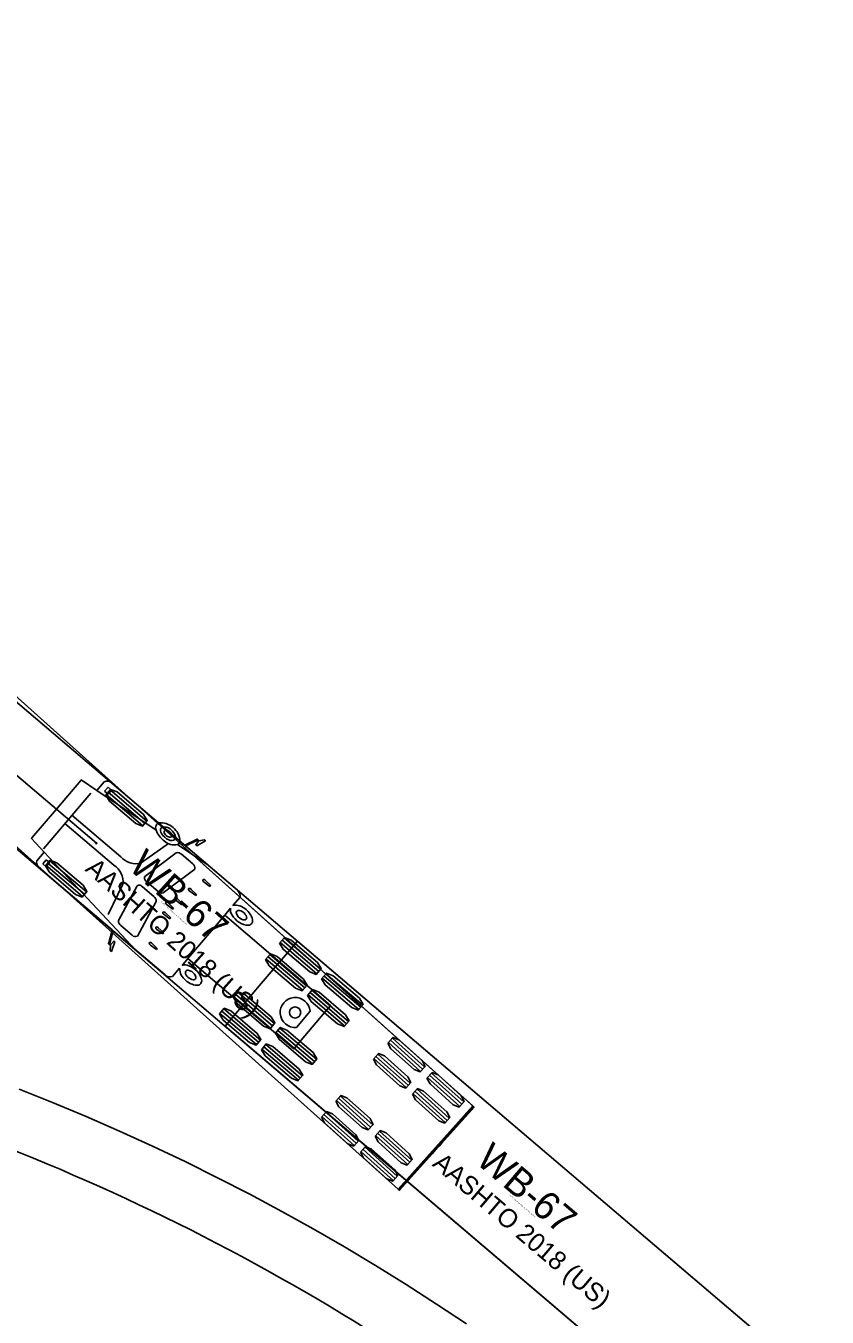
# Model space of a CAD drawing. Extents: x 973688 to 979179, y 703586 to 707602.
# Drawn here: x 974145.9 to 974206.9, y 707275.4 to 707373.8 of the extents above; entities that cross this region are included whole.
import ezdxf

# ---------------------------------------------------------------- set-up
doc = ezdxf.new("R2010")
doc.units = 0
doc.layers.add('0-NPLT', color=7, linetype='Continuous')
doc.layers.add('NO PLOT', color=7, linetype='Continuous')

msp = doc.modelspace()

# ---------------------------------------------------------------- linework, layer by layer
at = {"layer": '0-NPLT'}
for p, q in [((974173.518, 707296.32), (974175.975, 707294.117)), ((974173.518, 707296.32), (974175.975, 707294.117)), ((974173.671, 707296.49), (974176.128, 707294.287)), ((974173.671, 707296.49), (974176.128, 707294.287)), ((974173.824, 707296.661), (974176.281, 707294.458)), ((974173.824, 707296.661), (974176.281, 707294.458)), ((974172.417, 707295.091), (974174.874, 707292.888)), ((974172.417, 707295.091), (974174.874, 707292.888)), ((974172.57, 707295.262), (974175.027, 707293.059)), ((974172.57, 707295.262), (974175.027, 707293.059)), ((974172.723, 707295.432), (974175.18, 707293.229)), ((974172.723, 707295.432), (974175.18, 707293.229)), ((974176.65, 707293.82), (974179.107, 707291.617)), ((974176.65, 707293.82), (974179.107, 707291.617)), ((974176.803, 707293.991), (974179.26, 707291.788)), ((974176.803, 707293.991), (974179.26, 707291.788)), ((974175.701, 707292.762), (974178.158, 707290.559)), ((974175.701, 707292.762), (974178.158, 707290.559)), ((974176.497, 707293.649), (974178.954, 707291.446)), ((974176.497, 707293.649), (974178.954, 707291.446)), ((974169.557, 707291.902), (974172.014, 707289.699)), ((974169.557, 707291.902), (974172.014, 707289.699)), ((974169.71, 707292.073), (974172.167, 707289.87)), ((974169.71, 707292.073), (974172.167, 707289.87)), ((974169.863, 707292.243), (974172.32, 707290.04)), ((974169.863, 707292.243), (974172.32, 707290.04)), ((974175.395, 707292.421), (974177.852, 707290.218)), ((974175.395, 707292.421), (974177.852, 707290.218)), ((974175.548, 707292.591), (974178.005, 707290.388)), ((974175.548, 707292.591), (974178.005, 707290.388)), ((974168.609, 707290.844), (974171.066, 707288.641)), ((974168.609, 707290.844), (974171.066, 707288.641)), ((974168.762, 707291.015), (974171.219, 707288.812)), ((974168.762, 707291.015), (974171.219, 707288.812)), ((974179.94, 707291.485), (974174.266, 707285.156)), ((974179.94, 707291.485), (974174.266, 707285.156)), ((974168.456, 707290.674), (974170.913, 707288.471)), ((974168.456, 707290.674), (974170.913, 707288.471)), ((974172.536, 707289.232), (974174.993, 707287.029)), ((974172.536, 707289.232), (974174.993, 707287.029)), ((974172.689, 707289.402), (974175.146, 707287.199)), ((974172.689, 707289.402), (974175.146, 707287.199)), ((974172.842, 707289.573), (974175.299, 707287.37)), ((974172.842, 707289.573), (974175.299, 707287.37)), ((974171.434, 707288.003), (974173.891, 707285.8)), ((974171.434, 707288.003), (974173.891, 707285.8)), ((974171.587, 707288.174), (974174.044, 707285.971)), ((974171.587, 707288.174), (974174.044, 707285.971)), ((974171.74, 707288.345), (974174.197, 707286.142)), ((974171.74, 707288.345), (974174.197, 707286.142)), ((974176.978, 707288.076), (974176.801, 707287.878)), ((974176.978, 707288.076), (974176.801, 707287.878)), ((974177.156, 707288.274), (974177.103, 707288.321)), ((974177.156, 707288.274), (974177.103, 707288.321)), ((974177.51, 707288.669), (974177.333, 707288.471)), ((974177.51, 707288.669), (974177.333, 707288.471))]:
    msp.add_line(p, q, dxfattribs=at)
for points in [[(974091.775, 707370.47), (974093.475, 707368.994), (974180.045, 707291.391), (974174.371, 707285.062), (974174.274, 707285.149), (974174.274, 707285.149)], [(974091.775, 707370.47), (974093.475, 707368.994), (974180.045, 707291.391), (974174.371, 707285.062), (974174.274, 707285.149), (974174.274, 707285.149)], [(974174.274, 707285.149), (974119.818, 707333.965), (974115.987, 707337.353), (974112.281, 707340.555), (974110.488, 707342.064), (974108.732, 707343.506), (974107.011, 707344.881), (974105.317, 707346.189), (974103.645, 707347.433), (974101.988, 707348.612), (974100.348, 707349.725), (974098.726, 707350.769), (974097.122, 707351.743), (974095.538, 707352.645), (974093.977, 707353.475), (974092.437, 707354.233)], [(974174.274, 707285.149), (974119.818, 707333.965), (974115.987, 707337.353), (974112.281, 707340.555), (974110.488, 707342.064), (974108.732, 707343.506), (974107.011, 707344.881), (974105.317, 707346.189), (974103.645, 707347.433), (974101.988, 707348.612), (974100.348, 707349.725), (974098.726, 707350.769), (974097.122, 707351.743), (974095.538, 707352.645), (974093.977, 707353.475), (974092.437, 707354.233)], [(974179.978, 707291.421), (974179.992, 707291.437), (974179.94, 707291.484), (974175.721, 707295.268), (974140.585, 707326.772), (974137.748, 707323.608), (974134.91, 707320.444), (974170.046, 707288.94), (974174.266, 707285.157), (974174.319, 707285.11), (974174.333, 707285.126)], [(974179.978, 707291.421), (974179.992, 707291.437), (974179.94, 707291.484), (974175.721, 707295.268), (974140.585, 707326.772), (974137.748, 707323.608), (974134.91, 707320.444), (974170.046, 707288.94), (974174.266, 707285.157), (974174.319, 707285.11), (974174.333, 707285.126)], [(974145.394, 707292.754), (974147.934, 707291.742), (974150.486, 707290.678), (974153.02, 707289.573), (974155.535, 707288.429), (974158.03, 707287.245), (974160.505, 707286.022), (974162.958, 707284.76), (974165.389, 707283.459), (974167.797, 707282.122), (974170.182, 707280.746), (974172.543, 707279.334), (974174.88, 707277.886), (974177.192, 707276.401), (974179.478, 707274.881)], [(974145.394, 707292.754), (974147.934, 707291.742), (974150.486, 707290.678), (974153.02, 707289.573), (974155.535, 707288.429), (974158.03, 707287.245), (974160.505, 707286.022), (974162.958, 707284.76), (974165.389, 707283.459), (974167.797, 707282.122), (974170.182, 707280.746), (974172.543, 707279.334), (974174.88, 707277.886), (974177.192, 707276.401), (974179.478, 707274.881)], [(974177.384, 707288.422), (974177.562, 707288.621), (974177.562, 707288.622), (974177.51, 707288.669), (974177.534, 707288.696), (974179.961, 707291.403), (974179.962, 707291.403)], [(974177.384, 707288.422), (974177.562, 707288.621), (974177.562, 707288.622), (974177.51, 707288.669), (974177.534, 707288.696), (974179.961, 707291.403), (974179.962, 707291.403)], [(974174.35, 707285.144), (974174.35, 707285.145), (974176.777, 707287.851), (974176.801, 707287.878), (974176.853, 707287.831), (974176.854, 707287.832), (974177.033, 707288.031)], [(974174.35, 707285.144), (974174.35, 707285.145), (974176.777, 707287.851), (974176.801, 707287.878), (974176.853, 707287.831), (974176.854, 707287.832), (974177.033, 707288.031)], [(974176.983, 707288.081), (974177.331, 707288.469)], [(974176.983, 707288.081), (974177.331, 707288.469)]]:
    msp.add_lwpolyline(points, dxfattribs=at)
for points in [[(974173.481, 707296.277), (974173.862, 707296.703), (974174.321, 707296.523), (974176.09, 707294.937), (974176.319, 707294.5), (974175.937, 707294.074), (974175.478, 707294.254), (974173.709, 707295.841)], [(974173.481, 707296.277), (974173.862, 707296.703), (974174.321, 707296.523), (974176.09, 707294.937), (974176.319, 707294.5), (974175.937, 707294.074), (974175.478, 707294.254), (974173.709, 707295.841)], [(974172.379, 707295.049), (974172.761, 707295.475), (974173.22, 707295.295), (974174.989, 707293.708), (974175.218, 707293.272), (974174.836, 707292.846), (974174.377, 707293.026), (974172.608, 707294.612)], [(974172.379, 707295.049), (974172.761, 707295.475), (974173.22, 707295.295), (974174.989, 707293.708), (974175.218, 707293.272), (974174.836, 707292.846), (974174.377, 707293.026), (974172.608, 707294.612)], [(974176.459, 707293.607), (974176.841, 707294.033), (974177.3, 707293.853), (974179.069, 707292.267), (974179.297, 707291.83), (974178.916, 707291.404), (974178.457, 707291.584), (974176.688, 707293.17)], [(974176.459, 707293.607), (974176.841, 707294.033), (974177.3, 707293.853), (974179.069, 707292.267), (974179.297, 707291.83), (974178.916, 707291.404), (974178.457, 707291.584), (974176.688, 707293.17)], [(974175.357, 707292.379), (974175.739, 707292.804), (974176.198, 707292.624), (974177.967, 707291.038), (974178.196, 707290.601), (974177.814, 707290.176), (974177.355, 707290.356), (974175.586, 707291.942)], [(974175.357, 707292.379), (974175.739, 707292.804), (974176.198, 707292.624), (974177.967, 707291.038), (974178.196, 707290.601), (974177.814, 707290.176), (974177.355, 707290.356), (974175.586, 707291.942)], [(974169.52, 707291.86), (974169.901, 707292.286), (974170.36, 707292.106), (974172.129, 707290.519), (974172.358, 707290.083), (974171.977, 707289.657), (974171.517, 707289.837), (974169.748, 707291.423)], [(974169.52, 707291.86), (974169.901, 707292.286), (974170.36, 707292.106), (974172.129, 707290.519), (974172.358, 707290.083), (974171.977, 707289.657), (974171.517, 707289.837), (974169.748, 707291.423)], [(974168.418, 707290.631), (974168.8, 707291.057), (974169.259, 707290.877), (974171.028, 707289.291), (974171.257, 707288.854), (974170.875, 707288.428), (974170.416, 707288.608), (974168.647, 707290.195)], [(974168.418, 707290.631), (974168.8, 707291.057), (974169.259, 707290.877), (974171.028, 707289.291), (974171.257, 707288.854), (974170.875, 707288.428), (974170.416, 707288.608), (974168.647, 707290.195)], [(974172.498, 707289.189), (974172.88, 707289.615), (974173.339, 707289.435), (974175.108, 707287.849), (974175.337, 707287.412), (974174.955, 707286.986), (974174.496, 707287.167), (974172.727, 707288.753)], [(974172.498, 707289.189), (974172.88, 707289.615), (974173.339, 707289.435), (974175.108, 707287.849), (974175.337, 707287.412), (974174.955, 707286.986), (974174.496, 707287.167), (974172.727, 707288.753)], [(974171.396, 707287.961), (974171.778, 707288.387), (974172.237, 707288.207), (974174.006, 707286.621), (974174.235, 707286.184), (974173.853, 707285.758), (974173.394, 707285.938), (974171.625, 707287.524)], [(974171.396, 707287.961), (974171.778, 707288.387), (974172.237, 707288.207), (974174.006, 707286.621), (974174.235, 707286.184), (974173.853, 707285.758), (974173.394, 707285.938), (974171.625, 707287.524)]]:
    msp.add_lwpolyline(points, close=True, dxfattribs=at)
for centre in [(974179.995, 707291.39), (974179.995, 707291.39), (974174.367, 707285.112), (974174.367, 707285.112)]:
    msp.add_circle(centre, 0.0266, dxfattribs=at)
for centre, radius, start, end in [((974082.791, 707131.948), 168.088, 48.27288, 72.23933), ((974082.791, 707131.948), 168.088, 48.27288, 72.23933), ((974181.483, 707290.071), 2.022, 138.11946, 138.80322), ((974181.483, 707290.071), 2.022, 138.11946, 138.80322), ((974177.006, 707288.054), 0.0353, 141.45563, 319.80529), ((974177.006, 707288.054), 0.0353, 141.45563, 319.80529), ((974177.006, 707288.054), 0.0352, 318.14472, 137.14513), ((974177.006, 707288.054), 0.0352, 318.14472, 137.14513), ((974177.357, 707288.446), 0.0352, 139.09378, 318.09419), ((974177.357, 707288.446), 0.0352, 139.09378, 318.09419), ((974177.358, 707288.446), 0.0354, 322.41099, 134.59646), ((974177.358, 707288.446), 0.0354, 322.41099, 134.59646), ((974174.367, 707285.112), 0.0363, 157.1969, 118.35825), ((974174.367, 707285.112), 0.0363, 157.1969, 118.35825)]:
    msp.add_arc(centre, radius, start, end, dxfattribs=at)
at = {"layer": 'NO PLOT'}
for p, q in [((974151.267, 707311.497), (974078.117, 707373.753)), ((974155.816, 707312.493), (974151.31, 707315.518)), ((974152.162, 707315.779), (974151.894, 707315.465)), ((974151.894, 707315.465), (974152.165, 707315.234)), ((974152.433, 707315.548), (974152.162, 707315.779)), ((974152.165, 707315.234), (974152.433, 707315.548)), ((974152.166, 707315.382), (974154.958, 707313.006)), ((974152.315, 707315.557), (974155.107, 707313.18)), ((974150.844, 707315.319), (974147.239, 707311.082)), ((974152.018, 707315.208), (974154.81, 707312.831)), ((974149.406, 707313.629), (974153.131, 707310.458)), ((974148.865, 707312.993), (974152.59, 707309.823)), ((974154.68, 707309.996), (974156.772, 707311.473)), ((974159.054, 707311.644), (974159.072, 707311.666)), ((974159.072, 707311.666), (974159.099, 707311.672)), ((974154.27, 707303.36), (974147.304, 707310.812)), ((974157.357, 707310.77), (974154.963, 707308.952)), ((974159.779, 707309.833), (974157.449, 707311.397)), ((974158.607, 707309.923), (974157.746, 707310.656)), ((974158.066, 707311.291), (974157.99, 707311.356)), ((974147.183, 707309.929), (974147.45, 707310.243)), ((974147.454, 707309.698), (974147.183, 707309.929)), ((974147.427, 707309.814), (974150.219, 707307.437)), ((974147.45, 707310.243), (974147.721, 707310.013)), ((974147.721, 707310.013), (974147.454, 707309.698)), ((974147.575, 707309.988), (974150.367, 707307.612)), ((974147.724, 707310.163), (974150.516, 707307.786)), ((974156.367, 707307.714), (974158.76, 707309.532)), ((974155.116, 707308.561), (974155.977, 707307.828)), ((974159.919, 707308.199), (974159.475, 707308.525)), ((974159.584, 707308.653), (974159.978, 707308.267)), ((974153.294, 707308.367), (974152.177, 707306.078)), ((974152.958, 707305.602), (974154.37, 707308.255)), ((974154.781, 707308.166), (974155.642, 707307.433)), ((974158.837, 707307.522), (974158.393, 707307.848)), ((974158.502, 707307.976), (974158.895, 707307.59)), ((974158.895, 707307.59), (974158.837, 707307.522)), ((974159.978, 707308.267), (974159.919, 707308.199)), ((974155.816, 707307.068), (974154.404, 707304.414)), ((974157.1, 707306.473), (974156.656, 707306.8)), ((974156.765, 707306.928), (974157.158, 707306.542)), ((974157.158, 707306.542), (974157.1, 707306.473)), ((974157.793, 707306.811), (974157.349, 707307.138)), ((974157.458, 707307.266), (974157.851, 707306.88)), ((974157.851, 707306.88), (974157.793, 707306.811)), ((974156.877, 707305.735), (974156.433, 707306.062)), ((974156.542, 707306.19), (974156.935, 707305.804)), ((974156.935, 707305.804), (974156.877, 707305.735)), ((974161.047, 707306.016), (974158.24, 707302.719)), ((974152.557, 707304.818), (974152.481, 707304.883)), ((974153.994, 707304.503), (974153.133, 707305.236)), ((974156.343, 707304.592), (974155.879, 707304.934)), ((974155.988, 707305.062), (974156.401, 707304.66)), ((974156.401, 707304.66), (974156.343, 707304.592)), ((974152.348, 707303.766), (974152.346, 707303.738)), ((974152.367, 707303.786), (974152.348, 707303.766)), ((974155.847, 707303.415), (974155.403, 707303.741)), ((974155.512, 707303.869), (974155.906, 707303.483)), ((974165.268, 707303.93), (974168.061, 707301.554)), ((974165.417, 707304.105), (974168.209, 707301.728)), ((974165.565, 707304.279), (974168.358, 707301.903)), ((974155.906, 707303.483), (974155.847, 707303.415)), ((974164.199, 707302.674), (974166.991, 707300.297)), ((974164.347, 707302.848), (974167.14, 707300.472)), ((974164.496, 707303.023), (974167.288, 707300.646)), ((974168.467, 707301.208), (974171.259, 707298.832)), ((974168.615, 707301.383), (974171.407, 707299.006)), ((974168.764, 707301.557), (974171.556, 707299.181)), ((974161.747, 707299.793), (974164.539, 707297.416)), ((974161.895, 707299.967), (974164.688, 707297.591)), ((974162.044, 707300.142), (974164.836, 707297.765)), ((974167.397, 707299.952), (974170.19, 707297.575)), ((974167.546, 707300.126), (974170.338, 707297.75)), ((974167.694, 707300.301), (974170.487, 707297.924)), ((974160.826, 707298.711), (974163.618, 707296.334)), ((974160.974, 707298.885), (974163.767, 707296.509)), ((974166.509, 707297.47), (974167.556, 707298.701)), ((974160.677, 707298.536), (974163.47, 707296.16)), ((974164.945, 707297.071), (974167.737, 707294.694)), ((974165.094, 707297.245), (974167.886, 707294.869)), ((974165.242, 707297.42), (974168.035, 707295.043)), ((974163.876, 707295.814), (974166.668, 707293.438)), ((974164.024, 707295.989), (974166.817, 707293.612)), ((974164.173, 707296.163), (974166.965, 707293.787))]:
    msp.add_line(p, q, dxfattribs=at)
for points in [[(974090.217, 707369.015), (974206.948, 707269.689), (974201.439, 707263.216), (974201.341, 707263.299), (974201.341, 707263.299)], [(974201.341, 707263.299), (974117.082, 707334.995), (974113.179, 707338.264), (974109.412, 707341.341), (974107.59, 707342.787), (974105.806, 707344.168), (974104.057, 707345.482), (974102.335, 707346.731), (974100.634, 707347.916), (974098.951, 707349.037), (974097.285, 707350.092), (974095.639, 707351.077), (974094.014, 707351.993), (974092.411, 707352.837)], [(974146.744, 707310.153), (974147.299, 707310.805), (974147.303, 707310.813), (974146.324, 707311.861), (974146.365, 707311.909), (974148.221, 707314.089), (974150.076, 707316.27), (974150.118, 707316.318), (974151.308, 707315.519), (974151.315, 707315.524), (974151.87, 707316.177)], [(974152.458, 707316.064), (974155.995, 707313.054)], [(974157.659, 707311.637), (974157.984, 707311.361), (974157.999, 707311.36), (974158.901, 707311.781)], [(974159.032, 707311.728), (974159.098, 707311.673), (974159.101, 707311.673), (974159.488, 707311.76), (974159.491, 707311.76), (974159.581, 707311.684), (974159.581, 707311.682), (974158.918, 707311.301), (974158.84, 707311.367), (974159.054, 707311.643), (974159.054, 707311.644), (974158.992, 707311.695), (974158.992, 707311.696), (974158.991, 707311.696), (974158.955, 707311.711), (974158.955, 707311.711), (974158.066, 707311.291), (974162.008, 707307.936)], [(974152.207, 707303.915), (974152.478, 707304.873), (974152.475, 707304.888), (974146.948, 707309.591)], [(974161.492, 707306.539), (974161.047, 707306.017), (974161.228, 707305.862), (974169.119, 707299.146), (974167.716, 707297.497), (974166.313, 707295.849), (974158.422, 707302.564), (974158.24, 707302.718), (974157.795, 707302.196)], [(974162.222, 707307.398), (974161.675, 707306.754)], [(974156.499, 707301.463), (974152.557, 707304.818), (974152.285, 707303.873), (974152.285, 707303.873), (974152.305, 707303.84), (974152.305, 707303.84), (974152.306, 707303.839), (974152.366, 707303.787), (974152.368, 707303.787), (974152.605, 707304.042), (974152.684, 707303.975), (974152.413, 707303.26), (974152.412, 707303.259), (974152.321, 707303.336), (974152.321, 707303.34), (974152.346, 707303.736), (974152.345, 707303.739), (974152.28, 707303.795)], [(974206.88, 707269.717), (974206.894, 707269.734), (974206.84, 707269.78), (974202.525, 707273.453), (974166.587, 707304.039), (974163.832, 707300.803), (974161.078, 707297.566), (974197.016, 707266.98), (974201.332, 707263.308), (974201.386, 707263.262), (974201.4, 707263.279)], [(974157.613, 707301.981), (974157.065, 707301.338)]]:
    msp.add_lwpolyline(points, dxfattribs=at)
for points in [[(974151.981, 707315.164), (974152.351, 707315.6), (974152.854, 707315.399), (974154.864, 707313.688), (974155.144, 707313.224), (974154.773, 707312.788), (974154.27, 707312.99), (974152.26, 707314.701)], [(974147.39, 707309.77), (974147.761, 707310.206), (974148.263, 707310.004), (974150.274, 707308.293), (974150.553, 707307.829), (974150.182, 707307.394), (974149.679, 707307.595), (974147.669, 707309.306)], [(974165.231, 707303.887), (974165.602, 707304.323), (974166.105, 707304.121), (974168.115, 707302.41), (974168.394, 707301.946), (974168.024, 707301.511), (974167.521, 707301.712), (974165.511, 707303.423)], [(974164.162, 707302.631), (974164.533, 707303.066), (974165.035, 707302.865), (974167.046, 707301.154), (974167.325, 707300.69), (974166.954, 707300.254), (974166.452, 707300.456), (974164.441, 707302.167)], [(974168.43, 707301.165), (974168.801, 707301.601), (974169.303, 707301.399), (974171.314, 707299.688), (974171.593, 707299.224), (974171.222, 707298.789), (974170.72, 707298.99), (974168.709, 707300.701)], [(974161.71, 707299.749), (974162.081, 707300.185), (974162.583, 707299.984), (974164.594, 707298.273), (974164.873, 707297.809), (974164.502, 707297.373), (974164, 707297.574), (974161.989, 707299.286)], [(974167.36, 707299.908), (974167.731, 707300.344), (974168.234, 707300.143), (974170.244, 707298.432), (974170.523, 707297.968), (974170.153, 707297.532), (974169.65, 707297.733), (974167.64, 707299.445)], [(974160.641, 707298.493), (974161.011, 707298.929), (974161.514, 707298.727), (974163.524, 707297.016), (974163.804, 707296.552), (974163.433, 707296.116), (974162.93, 707296.318), (974160.92, 707298.029)], [(974164.908, 707297.027), (974165.279, 707297.463), (974165.782, 707297.261), (974167.792, 707295.55), (974168.071, 707295.086), (974167.701, 707294.651), (974167.198, 707294.852), (974165.188, 707296.563)], [(974163.839, 707295.771), (974164.21, 707296.206), (974164.712, 707296.005), (974166.723, 707294.294), (974167.002, 707293.83), (974166.631, 707293.394), (974166.129, 707293.596), (974164.118, 707295.307)]]:
    msp.add_lwpolyline(points, close=True, dxfattribs=at)
for centre, radius in [((974151.267, 707311.497), 0.0417), ((974166.412, 707298.607), 0.424)]:
    msp.add_circle(centre, radius, dxfattribs=at)
for centre, radius, start, end in [((974152.092, 707315.744), 0.486, 41.18554, 117.13665), ((974156.204, 707312.668), 0.425, 117.66255, 204.19891), ((974157.422, 707313.063), 1.704, 199.5203, 235.42836), ((974156.131, 707311.53), 1.53, 4.09235, 95.1014), ((974156.516, 707312.47), 0.366, 147.65195, 220.13294), ((974156.487, 707312.097), 0.634, 40.18347, 116.18519), ((974156.588, 707312.359), 0.158, 144.57083, 206.08358), ((974156.592, 707312.271), 0.223, 56.83451, 126.43701), ((974156.468, 707311.922), 0.589, 22.35514, 65.33785), ((974156.32, 707311.708), 1.03, 22.42326, 50.80977), ((974157.259, 707312.842), 1.189, 210.73081, 246.62013), ((974156.978, 707312.512), 0.575, 202.67473, 239.24506), ((974157.211, 707312.508), 1.136, 228.30415, 282.10672), ((974156.857, 707312.214), 0.263, 228.53452, 302.43645), ((974156.997, 707312.137), 0.44, 241.39386, 305.2067), ((974156.855, 707312.084), 0.17, 327.26867, 21.33301), ((974156.99, 707311.957), 0.317, 325.44981, 27.04221), ((974157.319, 707311.719), 0.347, 291.92682, 346.73741), ((974158.948, 707311.758), 0.0522, 48.48221, 153.33683), ((974158.927, 707311.705), 0.108, 12.57594, 58.75844), ((974154.272, 707311.457), 1.517, 221.17966, 285.60707), ((974157.458, 707310.397), 0.387, 42.0348, 105.26676), ((974147.206, 707310.003), 0.486, 162.06257, 238.01368), ((974151.787, 707308.536), 1.517, 353.59215, 58.01957), ((974158.444, 707309.633), 0.332, 342.25621, 60.67821), ((974155.234, 707308.833), 0.296, 156.31837, 246.61605), ((974159.56, 707308.689), 0.184, 170.75441, 242.64643), ((974159.447, 707308.578), 0.157, 28.94397, 116.05363), ((974154.531, 707308.007), 0.296, 32.58318, 122.88085), ((974156.265, 707308.087), 0.387, 222.03725, 285.26431), ((974158.477, 707308.012), 0.184, 170.75441, 242.64643), ((974158.364, 707307.9), 0.157, 28.94397, 116.05363), ((974161.607, 707307.465), 0.619, 353.75992, 49.60163), ((974155.432, 707307.108), 0.387, 353.93491, 57.16197), ((974156.709, 707306.947), 0.157, 163.14559, 250.25525), ((974156.628, 707306.852), 0.157, 28.94397, 116.05363), ((974157.434, 707307.301), 0.184, 170.75441, 242.64643), ((974157.321, 707307.19), 0.157, 28.94397, 116.05363), ((974162.212, 707306.429), 0.729, 171.27713, 213.79112), ((974161.871, 707305.635), 1.136, 45.17838, 99.96967), ((974153.343, 707305.561), 0.387, 173.93246, 237.16443), ((974156.486, 707306.209), 0.157, 163.14559, 250.25525), ((974156.394, 707306.08), 0.184, 36.55279, 108.44481), ((974163.09, 707306.914), 1.73, 210.97446, 235.77297), ((974162.096, 707306.206), 0.169, 101.04657, 201.16529), ((974162.634, 707306.374), 0.732, 198.19135, 244.42579), ((974162.106, 707305.851), 0.522, 47.43012, 94.59425), ((974162.519, 707306.015), 0.362, 236.26207, 285.30305), ((974162.075, 707305.693), 0.664, 16.47407, 54.69578), ((974162.55, 707305.825), 0.172, 292.14741, 19.29801), ((974161.794, 707305.33), 1.416, 14.6036, 51.67146), ((974162.832, 707305.59), 0.346, 279.19386, 16.20691), ((974155.952, 707305.066), 0.157, 163.14559, 250.25525), ((974155.86, 707304.936), 0.184, 36.55279, 108.44481), ((974162.811, 707306.382), 1.136, 232.3149, 273.83565), ((974152.237, 707303.873), 0.0522, 125.8624, 230.71701), ((974152.286, 707303.902), 0.108, 220.44078, 266.62328), ((974154.254, 707304.71), 0.332, 218.52101, 296.94302), ((974155.456, 707303.889), 0.157, 163.14559, 250.25525), ((974155.365, 707303.759), 0.184, 36.55279, 108.44481), ((974158.749, 707301.966), 1.136, 179.22955, 234.02084), ((974158.02, 707301.503), 0.729, 65.4081, 107.92209), ((974158.221, 707301.653), 0.169, 78.03394, 178.15266), ((974158.573, 707301.7), 0.522, 184.60498, 231.7691), ((974158.142, 707301.095), 0.732, 34.77343, 81.00787), ((974157.681, 707300.558), 1.73, 43.42625, 68.22476), ((974158.161, 707300.919), 1.136, 5.36357, 46.88432), ((974156.9, 707301.935), 0.619, 229.59759, 285.4393), ((974159.038, 707302.091), 1.416, 227.52776, 264.59562), ((974158.724, 707301.756), 0.664, 224.50344, 262.72516), ((974158.67, 707301.266), 0.172, 259.90121, 347.05181), ((974158.478, 707301.266), 0.362, 353.89617, 42.93715), ((974158.946, 707301.025), 0.346, 262.99231, 0.00536), ((974166.417, 707298.609), 1.143, 4.59961, 274.59961)]:
    msp.add_arc(centre, radius, start, end, dxfattribs=at)
for centre, major_axis, start_param, end_param in [((974158.966, 707311.756), (-0.0596, 0.0507), 0.569648, 1.840391), ((974158.966, 707311.756), (-0.0596, 0.0507), 2.398717, 3.668019), ((974152.242, 707303.855), (0.0596, -0.0507), 1.301202, 2.571945), ((974152.242, 707303.855), (-0.0596, 0.0507), 2.615166, 3.884468)]:
    msp.add_ellipse(centre, major_axis=major_axis, ratio=0.544872, start_param=start_param, end_param=end_param, dxfattribs=at)

# ---------------------------------------------------------------- texts
at = {"layer": '0-NPLT'}
for s, height, p in [('WB-67', 2.125, (974153.636, 707309.59)), ('WB-67', 2.125, (974153.636, 707309.59)), ('AASHTO 2018 (US)', 1.41667, (974150.348, 707309.447)), ('AASHTO 2018 (US)', 1.41667, (974150.348, 707309.447)), ('(c) 2021 Transoft Solutions, Inc. All rights reserved.', 0.085, (974156.16, 707307.042)), ('(c) 2021 Transoft Solutions, Inc. All rights reserved.', 0.085, (974156.16, 707307.042))]:
    msp.add_text(s, height=height, rotation=318.11946, dxfattribs=at).set_placement(p)
at = {"layer": 'NO PLOT'}
for s, height, p in [('WB-67', 2.125, (974180.077, 707287.2)), ('AASHTO 2018 (US)', 1.41667, (974176.794, 707286.972)), ('(c) 2021 Transoft Solutions, Inc. All rights reserved.', 0.085, (974182.666, 707284.718))]:
    msp.add_text(s, height=height, rotation=319.59961, dxfattribs=at).set_placement(p)

doc.saveas('drawing.dxf')
